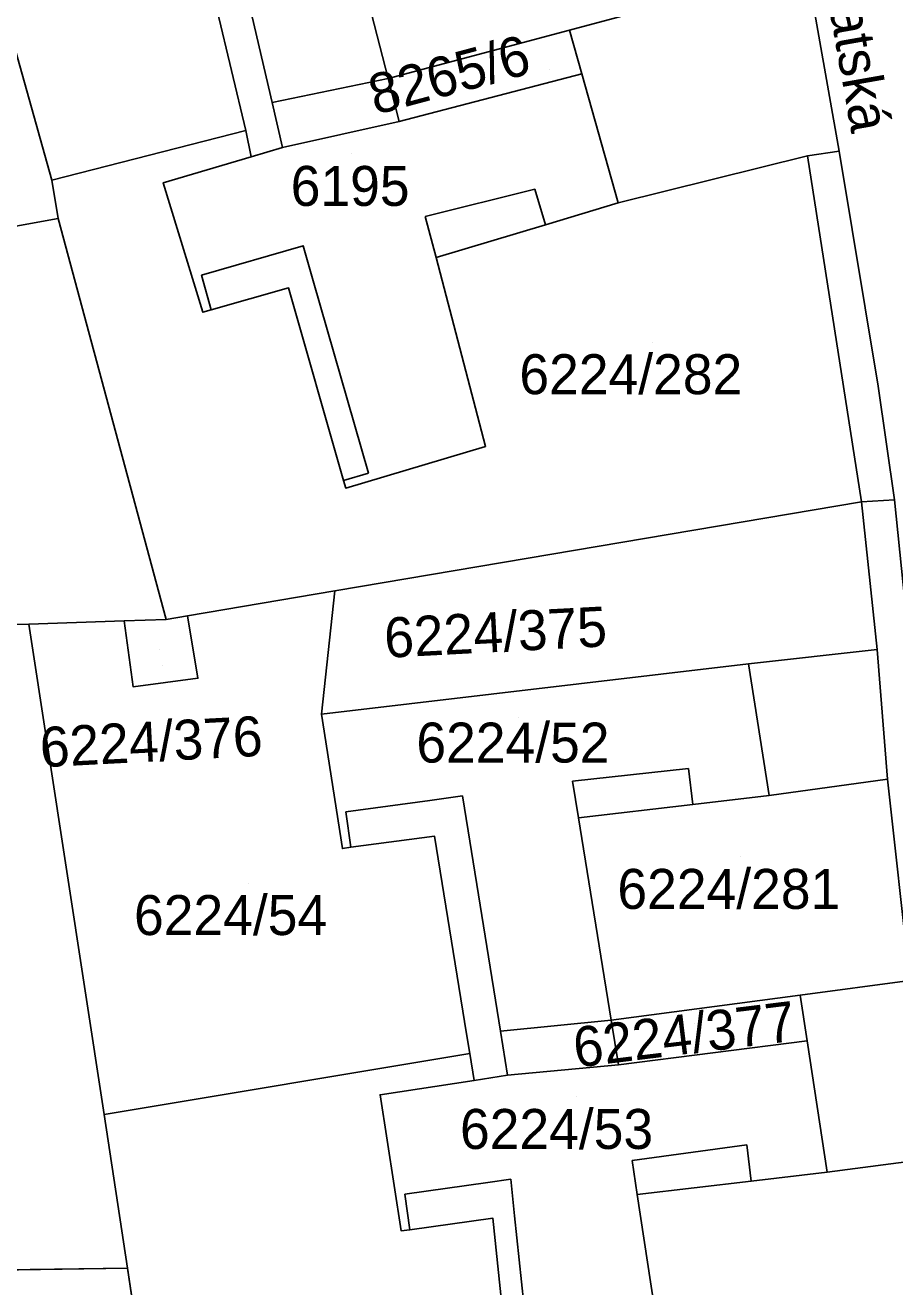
# Model space of a CAD drawing. Extents: x -266199 to -261993, y -1239047 to -1235108.
# Drawn here: x -263880.2 to -263836.6, y -1236026.7 to -1235963.6 of the extents above; entities that cross this region are included whole.
import ezdxf

# ---------------------------------------------------------------- set-up
doc = ezdxf.new("R2010")
doc.units = 0
for name, color, linetype in [('body_kn', 7, 'Continuous'), ('kladpar_druhypozemkov', 7, 'Continuous'), ('kladpar_hranice', 7, 'Continuous'), ('kladpar_parcelnecisla', 7, 'Continuous'), ('kladpar_plochy', 7, 'Continuous'), ('kladpar_sipky', 7, 'Continuous'), ('popisy', 7, 'Continuous'), ('zappar_hrandruhpozemk', 7, 'Continuous')]:
    doc.layers.add(name, color=color, linetype=linetype)

msp = doc.modelspace()

# ---------------------------------------------------------------- linework, layer by layer
at = {"layer": 'body_kn'}
for p, q in [((-263852.92, -1235963.79), (-263852.92, -1235963.79)), ((-263852.92, -1235963.79), (-263852.92, -1235963.79)), ((-263862, -1235966.22), (-263862, -1235966.22)), ((-263852.3, -1235965.99), (-263852.3, -1235965.99)), ((-263867.8, -1235967.42), (-263867.8, -1235967.42)), ((-263867.8, -1235967.42), (-263867.8, -1235967.42)), ((-263861.45, -1235968.36), (-263861.45, -1235968.36)), ((-263869.12, -1235968.81), (-263869.12, -1235968.81)), ((-263867.28, -1235969.66), (-263867.28, -1235969.66)), ((-263867.28, -1235969.66), (-263867.28, -1235969.66)), ((-263868.86, -1235970.14), (-263868.86, -1235970.14)), ((-263841.01, -1235970.09), (-263841.01, -1235970.09)), ((-263841.01, -1235970.09), (-263841.01, -1235970.09)), ((-263839.42, -1235969.85), (-263839.42, -1235969.85)), ((-263839.42, -1235969.85), (-263839.42, -1235969.85)), ((-263878.83, -1235971.31), (-263878.83, -1235971.31)), ((-263873.26, -1235971.43), (-263873.26, -1235971.43)), ((-263873.26, -1235971.43), (-263873.26, -1235971.43)), ((-263854.66, -1235971.76), (-263854.66, -1235971.76)), ((-263850.48, -1235972.43), (-263850.48, -1235972.43)), ((-263850.48, -1235972.43), (-263850.48, -1235972.43)), ((-263878.51, -1235973.22), (-263878.51, -1235973.22)), ((-263860.14, -1235973.12), (-263860.14, -1235973.12)), ((-263854.13, -1235973.53), (-263854.13, -1235973.53)), ((-263854.13, -1235973.53), (-263854.13, -1235973.53)), ((-263866.25, -1235974.58), (-263866.25, -1235974.58)), ((-263859.6, -1235975.17), (-263859.6, -1235975.17)), ((-263871.34, -1235976.06), (-263871.34, -1235976.06)), ((-263865.75, -1235976.34), (-263865.75, -1235976.34)), ((-263866.98, -1235976.69), (-263866.98, -1235976.69)), ((-263871.28, -1235977.91), (-263871.28, -1235977.91)), ((-263870.85, -1235977.79), (-263870.85, -1235977.79)), ((-263870.85, -1235977.79), (-263870.85, -1235977.79)), ((-263837.47, -1235981.61), (-263837.47, -1235981.61)), ((-263857.12, -1235984.63), (-263857.12, -1235984.63)), ((-263862.99, -1235985.96), (-263862.99, -1235985.96)), ((-263864.23, -1235986.33), (-263864.23, -1235986.33)), ((-263864.12, -1235986.71), (-263864.12, -1235986.71)), ((-263836.66, -1235987.3), (-263836.66, -1235987.3)), ((-263838.31, -1235987.4), (-263838.31, -1235987.4)), ((-263838.31, -1235987.4), (-263838.31, -1235987.4)), ((-263864.66, -1235991.85), (-263864.66, -1235991.85)), ((-263864.66, -1235991.85), (-263864.66, -1235991.85)), ((-263879.98, -1235993.52), (-263879.98, -1235993.52)), ((-263875.21, -1235993.35), (-263875.21, -1235993.35)), ((-263873.11, -1235993.28), (-263873.11, -1235993.28)), ((-263872.05, -1235993.1), (-263872.05, -1235993.1)), ((-263872.05, -1235993.1), (-263872.05, -1235993.1)), ((-263837.52, -1235994.78), (-263837.52, -1235994.78)), ((-263837.52, -1235994.78), (-263837.52, -1235994.78)), ((-263843.97, -1235995.5), (-263843.97, -1235995.5)), ((-263871.52, -1235996.22), (-263871.52, -1235996.22)), ((-263874.77, -1235996.65), (-263874.77, -1235996.65)), ((-263865.34, -1235998.02), (-263865.34, -1235998.02)), ((-263865.34, -1235998.02), (-263865.34, -1235998.02)), ((-263846.96, -1236000.74), (-263846.96, -1236000.74)), ((-263837.01, -1236001.27), (-263837.01, -1236001.27)), ((-263852.77, -1236001.37), (-263852.77, -1236001.37)), ((-263859.92, -1236002.34), (-263859.92, -1236002.34)), ((-263858.28, -1236002.11), (-263858.28, -1236002.11)), ((-263846.75, -1236002.53), (-263846.75, -1236002.53)), ((-263846.75, -1236002.53), (-263846.75, -1236002.53)), ((-263842.92, -1236002.08), (-263842.92, -1236002.08)), ((-263864.11, -1236002.9), (-263864.11, -1236002.9)), ((-263852.47, -1236003.2), (-263852.47, -1236003.2)), ((-263852.47, -1236003.2), (-263852.47, -1236003.2)), ((-263859.68, -1236004.12), (-263859.68, -1236004.12)), ((-263858, -1236003.85), (-263858, -1236003.85)), ((-263864.29, -1236004.74), (-263864.29, -1236004.74)), ((-263863.87, -1236004.68), (-263863.87, -1236004.68)), ((-263841.37, -1236012.08), (-263841.37, -1236012.08)), ((-263841.37, -1236012.08), (-263841.37, -1236012.08)), ((-263856.38, -1236013.88), (-263856.38, -1236013.88)), ((-263850.83, -1236013.33), (-263850.83, -1236013.33)), ((-263850.83, -1236013.33), (-263850.83, -1236013.33)), ((-263858.07, -1236014.01), (-263858.07, -1236014.01)), ((-263841.03, -1236014.36), (-263841.03, -1236014.36)), ((-263857.91, -1236015), (-263857.91, -1236015)), ((-263850.47, -1236015.57), (-263850.47, -1236015.57)), ((-263857.69, -1236016.34), (-263857.69, -1236016.34)), ((-263856.02, -1236016.08), (-263856.02, -1236016.08)), ((-263856.02, -1236016.08), (-263856.02, -1236016.08)), ((-263862.4, -1236017.06), (-263862.4, -1236017.06)), ((-263862.4, -1236017.06), (-263862.4, -1236017.06)), ((-263876.22, -1236018.04), (-263876.22, -1236018.04)), ((-263876.22, -1236018.04), (-263876.22, -1236018.04)), ((-263844.04, -1236019.56), (-263844.04, -1236019.56)), ((-263849.79, -1236020.35), (-263849.79, -1236020.35)), ((-263857.01, -1236021.45), (-263857.01, -1236021.45)), ((-263855.86, -1236021.29), (-263855.86, -1236021.29)), ((-263843.83, -1236021.38), (-263843.83, -1236021.38)), ((-263843.83, -1236021.38), (-263843.83, -1236021.38)), ((-263840.03, -1236020.93), (-263840.03, -1236020.93)), ((-263861.17, -1236022.03), (-263861.17, -1236022.03)), ((-263849.53, -1236022.05), (-263849.53, -1236022.05)), ((-263856.76, -1236023.23), (-263856.76, -1236023.23)), ((-263855.67, -1236023.12), (-263855.67, -1236023.12)), ((-263861.34, -1236023.87), (-263861.34, -1236023.87)), ((-263860.92, -1236023.81), (-263860.92, -1236023.81)), ((-263875.05, -1236025.74), (-263875.05, -1236025.74))]:
    msp.add_line(p, q, dxfattribs=at)
at = {"layer": 'kladpar_druhypozemkov'}
for p, q in [((-263853.94, -1235965.77), (-263853.94, -1235965.77)), ((-263863.83, -1235969.99), (-263863.83, -1235969.99)), ((-263848.76, -1235979.41), (-263848.76, -1235979.41)), ((-263855.15, -1235993.03), (-263855.15, -1235993.03)), ((-263873.45, -1235994.77), (-263873.45, -1235994.77)), ((-263855.48, -1235998.18), (-263855.48, -1235998.18)), ((-263844.35, -1236005.16), (-263844.35, -1236005.16)), ((-263868.98, -1236006.47), (-263868.98, -1236006.47)), ((-263846.64, -1236013.47), (-263846.64, -1236013.47)), ((-263852.56, -1236017.17), (-263852.56, -1236017.17))]:
    msp.add_line(p, q, dxfattribs=at)
at = {"layer": 'kladpar_hranice'}
for points in [[(-263873.84, -1235951.8), (-263878.17, -1235952.92), (-263876.36, -1235959.53), (-263875.84, -1235959.37), (-263871.69, -1235958.11), (-263870.56, -1235962.82), (-263869.12, -1235968.81), (-263878.83, -1235971.31), (-263882.83, -1235957.05), (-263886.74, -1235941.61), (-263875.54, -1235940.14), (-263873.86, -1235951.18), (-263873.84, -1235951.8)], [(-263857.03, -1235947.46), (-263855.31, -1235953.91), (-263859.01, -1235954.95), (-263864.5, -1235956.49), (-263862, -1235966.22), (-263861.45, -1235968.36), (-263867.28, -1235969.66), (-263868.86, -1235970.14), (-263869.12, -1235968.81), (-263870.56, -1235962.82), (-263871.69, -1235958.11), (-263875.84, -1235959.37), (-263876.36, -1235959.53), (-263878.17, -1235952.92), (-263873.84, -1235951.8), (-263857.03, -1235947.46)], [(-263855.31, -1235953.91), (-263844.3, -1235951.29), (-263842.67, -1235961.04), (-263852.92, -1235963.79), (-263862, -1235966.22), (-263864.5, -1235956.49), (-263859.01, -1235954.95), (-263855.31, -1235953.91)], [(-263919.11, -1235980.52), (-263922.95, -1235967.01), (-263882.83, -1235957.05), (-263878.83, -1235971.31), (-263878.51, -1235973.22), (-263902.26, -1235977.53), (-263903.32, -1235971.78), (-263904.49, -1235972.04), (-263904.91, -1235970.12), (-263905.23, -1235968.67), (-263907.68, -1235969.15), (-263907.98, -1235967.63), (-263915.25, -1235968.78), (-263914.99, -1235970.31), (-263913.41, -1235979.47), (-263919.11, -1235980.52)], [(-263833.28, -1236039.34), (-263835.05, -1236020.28), (-263840.03, -1236020.93), (-263841.03, -1236014.36), (-263841.37, -1236012.08), (-263835.89, -1236011.35), (-263837.01, -1236001.27), (-263842.92, -1236002.08), (-263843.97, -1235995.5), (-263837.52, -1235994.78), (-263838.31, -1235987.4), (-263841.01, -1235970.09), (-263850.48, -1235972.43), (-263852.3, -1235965.99), (-263852.92, -1235963.79), (-263842.67, -1235961.04)], [(-263852.92, -1235963.79), (-263852.3, -1235965.99), (-263861.45, -1235968.36), (-263862, -1235966.22), (-263852.92, -1235963.79)], [(-263873.26, -1235971.43), (-263868.86, -1235970.14), (-263867.28, -1235969.66), (-263861.45, -1235968.36), (-263852.3, -1235965.99), (-263850.48, -1235972.43), (-263854.13, -1235973.53), (-263859.6, -1235975.17), (-263857.12, -1235984.63), (-263864.12, -1235986.71), (-263864.23, -1235986.33), (-263866.98, -1235976.69), (-263870.85, -1235977.79), (-263871.28, -1235977.91), (-263873.26, -1235971.43)], [(-263850.48, -1235972.43), (-263841.01, -1235970.09), (-263838.31, -1235987.4), (-263864.66, -1235991.85), (-263872.05, -1235993.1), (-263873.11, -1235993.28), (-263878.51, -1235973.22), (-263878.83, -1235971.31), (-263869.12, -1235968.81), (-263868.86, -1235970.14), (-263873.26, -1235971.43), (-263871.28, -1235977.91), (-263870.85, -1235977.79), (-263866.98, -1235976.69), (-263864.23, -1235986.33), (-263864.12, -1235986.71), (-263857.12, -1235984.63), (-263859.6, -1235975.17), (-263854.13, -1235973.53), (-263850.48, -1235972.43)], [(-263919.11, -1235980.52), (-263913.41, -1235979.47), (-263911.87, -1235988.67), (-263911.57, -1235990.13), (-263904.18, -1235988.85), (-263904.43, -1235987.38), (-263901.98, -1235987.01), (-263902.43, -1235983.44), (-263901.19, -1235983.28), (-263902.26, -1235977.53), (-263878.51, -1235973.22), (-263873.11, -1235993.28), (-263875.21, -1235993.35), (-263879.98, -1235993.52), (-263915.46, -1235994.07), (-263917.55, -1235986.2), (-263919.11, -1235980.52)], [(-263838.31, -1235987.4), (-263837.52, -1235994.78), (-263843.97, -1235995.5), (-263865.34, -1235998.02), (-263864.66, -1235991.85), (-263838.31, -1235987.4)], [(-263864.66, -1235991.85), (-263865.34, -1235998.02), (-263864.29, -1236004.74), (-263863.87, -1236004.68), (-263859.68, -1236004.12), (-263858.07, -1236014.01), (-263857.91, -1236015), (-263876.22, -1236018.04), (-263879.98, -1235993.52), (-263875.21, -1235993.35), (-263874.77, -1235996.65), (-263871.52, -1235996.22), (-263872.05, -1235993.1), (-263864.66, -1235991.85)], [(-263915.46, -1235994.07), (-263879.98, -1235993.52), (-263876.22, -1236018.04), (-263875.05, -1236025.74), (-263907.95, -1236026.19), (-263915.46, -1235994.07)], [(-263872.05, -1235993.1), (-263871.52, -1235996.22), (-263874.77, -1235996.65), (-263875.21, -1235993.35), (-263873.11, -1235993.28), (-263872.05, -1235993.1)], [(-263865.34, -1235998.02), (-263843.97, -1235995.5), (-263842.92, -1236002.08), (-263846.75, -1236002.53), (-263852.47, -1236003.2), (-263850.83, -1236013.33), (-263850.47, -1236015.57), (-263856.02, -1236016.08), (-263857.69, -1236016.34), (-263857.91, -1236015), (-263858.07, -1236014.01), (-263859.68, -1236004.12), (-263863.87, -1236004.68), (-263864.29, -1236004.74), (-263865.34, -1235998.02)], [(-263852.47, -1236003.2), (-263846.75, -1236002.53), (-263842.92, -1236002.08), (-263837.01, -1236001.27), (-263835.89, -1236011.35), (-263841.37, -1236012.08), (-263850.83, -1236013.33), (-263852.47, -1236003.2)], [(-263841.37, -1236012.08), (-263841.03, -1236014.36), (-263850.47, -1236015.57), (-263850.83, -1236013.33), (-263841.37, -1236012.08)], [(-263862.4, -1236017.06), (-263857.69, -1236016.34), (-263856.02, -1236016.08), (-263850.47, -1236015.57), (-263841.03, -1236014.36), (-263840.03, -1236020.93), (-263843.83, -1236021.38), (-263849.53, -1236022.05), (-263847.98, -1236032.21), (-263854.63, -1236033.02), (-263855.72, -1236033.15), (-263856.76, -1236023.23), (-263860.92, -1236023.81), (-263861.34, -1236023.87), (-263862.4, -1236017.06)], [(-263876.22, -1236018.04), (-263857.91, -1236015), (-263857.69, -1236016.34), (-263862.4, -1236017.06), (-263861.34, -1236023.87), (-263860.92, -1236023.81), (-263856.76, -1236023.23), (-263855.72, -1236033.15), (-263859.59, -1236033.45), (-263860.72, -1236037), (-263861.02, -1236037.94), (-263861.24, -1236038.62), (-263873.21, -1236037.96), (-263875.05, -1236025.74), (-263876.22, -1236018.04)], [(-263835.05, -1236020.28), (-263833.28, -1236039.34), (-263860.75, -1236038.65), (-263861.24, -1236038.62), (-263861.02, -1236037.94), (-263854.11, -1236037.98), (-263854.63, -1236033.02), (-263847.98, -1236032.21), (-263849.53, -1236022.05), (-263843.83, -1236021.38), (-263840.03, -1236020.93), (-263835.05, -1236020.28)], [(-263873.21, -1236037.96), (-263872.31, -1236056.62), (-263901.98, -1236056.01), (-263903.98, -1236043.88), (-263907.95, -1236026.19), (-263875.05, -1236025.74), (-263873.21, -1236037.96)]]:
    msp.add_lwpolyline(points, dxfattribs=at)
at = {"layer": 'kladpar_plochy'}
for p, q in [((-263915.46, -1235994.07), (-263879.98, -1235993.52)), ((-263879.98, -1235993.52), (-263876.22, -1236018.04)), ((-263876.22, -1236018.04), (-263875.05, -1236025.74)), ((-263875.05, -1236025.74), (-263907.95, -1236026.19)), ((-263907.95, -1236026.19), (-263875.05, -1236025.74)), ((-263875.05, -1236025.74), (-263873.21, -1236037.96))]:
    msp.add_line(p, q, dxfattribs=at)
for points in [[(-263873.84, -1235951.8), (-263878.17, -1235952.92), (-263876.36, -1235959.53), (-263875.84, -1235959.37), (-263871.69, -1235958.11), (-263870.56, -1235962.82), (-263869.12, -1235968.81), (-263878.83, -1235971.31), (-263882.83, -1235957.05), (-263886.74, -1235941.61), (-263875.54, -1235940.14), (-263873.86, -1235951.18)], [(-263857.03, -1235947.46), (-263855.31, -1235953.91), (-263859.01, -1235954.95), (-263864.5, -1235956.49), (-263862, -1235966.22), (-263861.45, -1235968.36), (-263867.28, -1235969.66), (-263868.86, -1235970.14), (-263869.12, -1235968.81), (-263870.56, -1235962.82), (-263871.69, -1235958.11), (-263875.84, -1235959.37), (-263876.36, -1235959.53), (-263878.17, -1235952.92), (-263873.84, -1235951.8)], [(-263855.31, -1235953.91), (-263844.3, -1235951.29), (-263842.67, -1235961.04), (-263852.92, -1235963.79), (-263862, -1235966.22), (-263864.5, -1235956.49), (-263859.01, -1235954.95)], [(-263919.11, -1235980.52), (-263922.95, -1235967.01), (-263882.83, -1235957.05), (-263878.83, -1235971.31), (-263878.51, -1235973.22), (-263902.26, -1235977.53), (-263903.32, -1235971.78), (-263904.49, -1235972.04), (-263904.91, -1235970.12), (-263905.23, -1235968.67), (-263907.68, -1235969.15), (-263907.98, -1235967.63), (-263915.25, -1235968.78), (-263914.99, -1235970.31), (-263913.41, -1235979.47)], [(-263852.92, -1235963.79), (-263852.3, -1235965.99), (-263861.45, -1235968.36), (-263862, -1235966.22)], [(-263873.26, -1235971.43), (-263868.86, -1235970.14), (-263867.28, -1235969.66), (-263861.45, -1235968.36), (-263852.3, -1235965.99), (-263850.48, -1235972.43), (-263854.13, -1235973.53), (-263859.6, -1235975.17), (-263857.12, -1235984.63), (-263864.12, -1235986.71), (-263864.23, -1235986.33), (-263866.98, -1235976.69), (-263870.85, -1235977.79), (-263871.28, -1235977.91)], [(-263850.48, -1235972.43), (-263841.01, -1235970.09), (-263838.31, -1235987.4), (-263864.66, -1235991.85), (-263872.05, -1235993.1), (-263873.11, -1235993.28), (-263878.51, -1235973.22), (-263878.83, -1235971.31), (-263869.12, -1235968.81), (-263868.86, -1235970.14), (-263873.26, -1235971.43), (-263871.28, -1235977.91), (-263870.85, -1235977.79), (-263866.98, -1235976.69), (-263864.23, -1235986.33), (-263864.12, -1235986.71), (-263857.12, -1235984.63), (-263859.6, -1235975.17), (-263854.13, -1235973.53)], [(-263919.11, -1235980.52), (-263913.41, -1235979.47), (-263911.87, -1235988.67), (-263911.57, -1235990.13), (-263904.18, -1235988.85), (-263904.43, -1235987.38), (-263901.98, -1235987.01), (-263902.43, -1235983.44), (-263901.19, -1235983.28), (-263902.26, -1235977.53), (-263878.51, -1235973.22), (-263873.11, -1235993.28), (-263875.21, -1235993.35), (-263879.98, -1235993.52), (-263915.46, -1235994.07), (-263917.55, -1235986.2)], [(-263838.31, -1235987.4), (-263837.52, -1235994.78), (-263843.97, -1235995.5), (-263865.34, -1235998.02), (-263864.66, -1235991.85)], [(-263864.66, -1235991.85), (-263865.34, -1235998.02), (-263864.29, -1236004.74), (-263863.87, -1236004.68), (-263859.68, -1236004.12), (-263858.07, -1236014.01), (-263857.91, -1236015), (-263876.22, -1236018.04), (-263879.98, -1235993.52), (-263875.21, -1235993.35), (-263874.77, -1235996.65), (-263871.52, -1235996.22), (-263872.05, -1235993.1)], [(-263872.05, -1235993.1), (-263871.52, -1235996.22), (-263874.77, -1235996.65), (-263875.21, -1235993.35), (-263873.11, -1235993.28)], [(-263865.34, -1235998.02), (-263843.97, -1235995.5), (-263842.92, -1236002.08), (-263846.75, -1236002.53), (-263852.47, -1236003.2), (-263850.83, -1236013.33), (-263850.47, -1236015.57), (-263856.02, -1236016.08), (-263857.69, -1236016.34), (-263857.91, -1236015), (-263858.07, -1236014.01), (-263859.68, -1236004.12), (-263863.87, -1236004.68), (-263864.29, -1236004.74)], [(-263852.47, -1236003.2), (-263846.75, -1236002.53), (-263842.92, -1236002.08), (-263837.01, -1236001.27), (-263835.89, -1236011.35), (-263841.37, -1236012.08), (-263850.83, -1236013.33)], [(-263841.37, -1236012.08), (-263841.03, -1236014.36), (-263850.47, -1236015.57), (-263850.83, -1236013.33)], [(-263862.4, -1236017.06), (-263857.69, -1236016.34), (-263856.02, -1236016.08), (-263850.47, -1236015.57), (-263841.03, -1236014.36), (-263840.03, -1236020.93), (-263843.83, -1236021.38), (-263849.53, -1236022.05), (-263847.98, -1236032.21), (-263854.63, -1236033.02), (-263855.72, -1236033.15), (-263856.76, -1236023.23), (-263860.92, -1236023.81), (-263861.34, -1236023.87)], [(-263876.22, -1236018.04), (-263857.91, -1236015), (-263857.69, -1236016.34), (-263862.4, -1236017.06), (-263861.34, -1236023.87), (-263860.92, -1236023.81), (-263856.76, -1236023.23), (-263855.72, -1236033.15), (-263859.59, -1236033.45), (-263860.72, -1236037), (-263861.02, -1236037.94), (-263861.24, -1236038.62), (-263873.21, -1236037.96), (-263875.05, -1236025.74)], [(-263835.05, -1236020.28), (-263833.28, -1236039.34), (-263860.75, -1236038.65), (-263861.24, -1236038.62), (-263861.02, -1236037.94), (-263854.11, -1236037.98), (-263854.63, -1236033.02), (-263847.98, -1236032.21), (-263849.53, -1236022.05), (-263843.83, -1236021.38), (-263840.03, -1236020.93)]]:
    msp.add_lwpolyline(points, close=True, dxfattribs=at)
msp.add_lwpolyline([(-263833.28, -1236039.34), (-263835.05, -1236020.28), (-263840.03, -1236020.93), (-263841.03, -1236014.36), (-263841.37, -1236012.08), (-263835.89, -1236011.35), (-263837.01, -1236001.27), (-263842.92, -1236002.08), (-263843.97, -1235995.5), (-263837.52, -1235994.78), (-263838.31, -1235987.4), (-263841.01, -1235970.09), (-263850.48, -1235972.43), (-263852.3, -1235965.99), (-263852.92, -1235963.79), (-263842.67, -1235961.04)], dxfattribs=at)
at = {"layer": 'kladpar_sipky'}
msp.add_line((-263873.31, -1235995.6), (-263873.31, -1235995.6), dxfattribs=at)
at = {"layer": 'zappar_hrandruhpozemk'}
for p, q in [((-263870.08, -1235957.73), (-263867.8, -1235967.42)), ((-263867.8, -1235967.42), (-263862, -1235966.22)), ((-263867.28, -1235969.66), (-263867.8, -1235967.42)), ((-263841.01, -1235970.09), (-263839.42, -1235969.85)), ((-263839.42, -1235969.85), (-263837.47, -1235981.61)), ((-263854.66, -1235971.76), (-263860.14, -1235973.12)), ((-263854.13, -1235973.53), (-263854.66, -1235971.76)), ((-263860.14, -1235973.12), (-263859.6, -1235975.17)), ((-263865.75, -1235976.34), (-263862.99, -1235985.96)), ((-263837.47, -1235981.61), (-263836.66, -1235987.3)), ((-263862.99, -1235985.96), (-263864.23, -1235986.33)), ((-263837.52, -1235994.78), (-263837.01, -1236001.27)), ((-263846.96, -1236000.74), (-263852.77, -1236001.37)), ((-263846.75, -1236002.53), (-263846.96, -1236000.74)), ((-263852.77, -1236001.37), (-263852.47, -1236003.2)), ((-263859.92, -1236002.34), (-263864.11, -1236002.9)), ((-263864.11, -1236002.9), (-263863.87, -1236004.68)), ((-263850.83, -1236013.33), (-263856.38, -1236013.88)), ((-263844.04, -1236019.56), (-263849.79, -1236020.35)), ((-263843.83, -1236021.38), (-263844.04, -1236019.56)), ((-263849.79, -1236020.35), (-263849.53, -1236022.05)), ((-263857.01, -1236021.45), (-263861.17, -1236022.03)), ((-263861.17, -1236022.03), (-263860.92, -1236023.81))]:
    msp.add_line(p, q, dxfattribs=at)
for points in [[(-263843.97, -1235943.75), (-263842.73, -1235951.12), (-263841.02, -1235960.78), (-263839.42, -1235969.85)], [(-263870.85, -1235977.79), (-263871.34, -1235976.06), (-263866.25, -1235974.58), (-263865.75, -1235976.34)], [(-263838.31, -1235987.4), (-263836.66, -1235987.3), (-263835.87, -1235994.98), (-263835.28, -1236001.29)], [(-263856.02, -1236016.08), (-263856.38, -1236013.88), (-263858, -1236003.85), (-263858.28, -1236002.11), (-263859.92, -1236002.34)], [(-263854.63, -1236033.02), (-263855.67, -1236023.12), (-263855.86, -1236021.29), (-263857.01, -1236021.45)]]:
    msp.add_lwpolyline(points, dxfattribs=at)

# ---------------------------------------------------------------- texts
at = {"layer": 'kladpar_parcelnecisla'}
for s, rotation, p in [('8265/6', 15, (-263862.643, -1235968.046)), ('6224/375', 3, (-263862.144, -1235995.202)), ('6224/376', 3, (-263879.379, -1236000.679)), ('6224/377', 7, (-263852.601, -1236015.703))]:
    msp.add_text(s, height=2, rotation=rotation, dxfattribs=at).set_placement(p)
for s, p in [('6195', (-263866.876, -1235972.59)), ('6224/282', (-263855.43, -1235982.01)), ('6224/52', (-263860.586, -1236000.44)), ('6224/281', (-263850.524, -1236007.76)), ('6224/54', (-263874.719, -1236009.07)), ('6224/53', (-263858.402, -1236019.77))]:
    msp.add_text(s, height=2, dxfattribs=at).set_placement(p)
at = {"layer": 'popisy'}
msp.add_text('Vihorlatská', height=2, rotation=280, dxfattribs=at).set_placement((-263841.102, -1235955.977))

doc.saveas('drawing.dxf')
